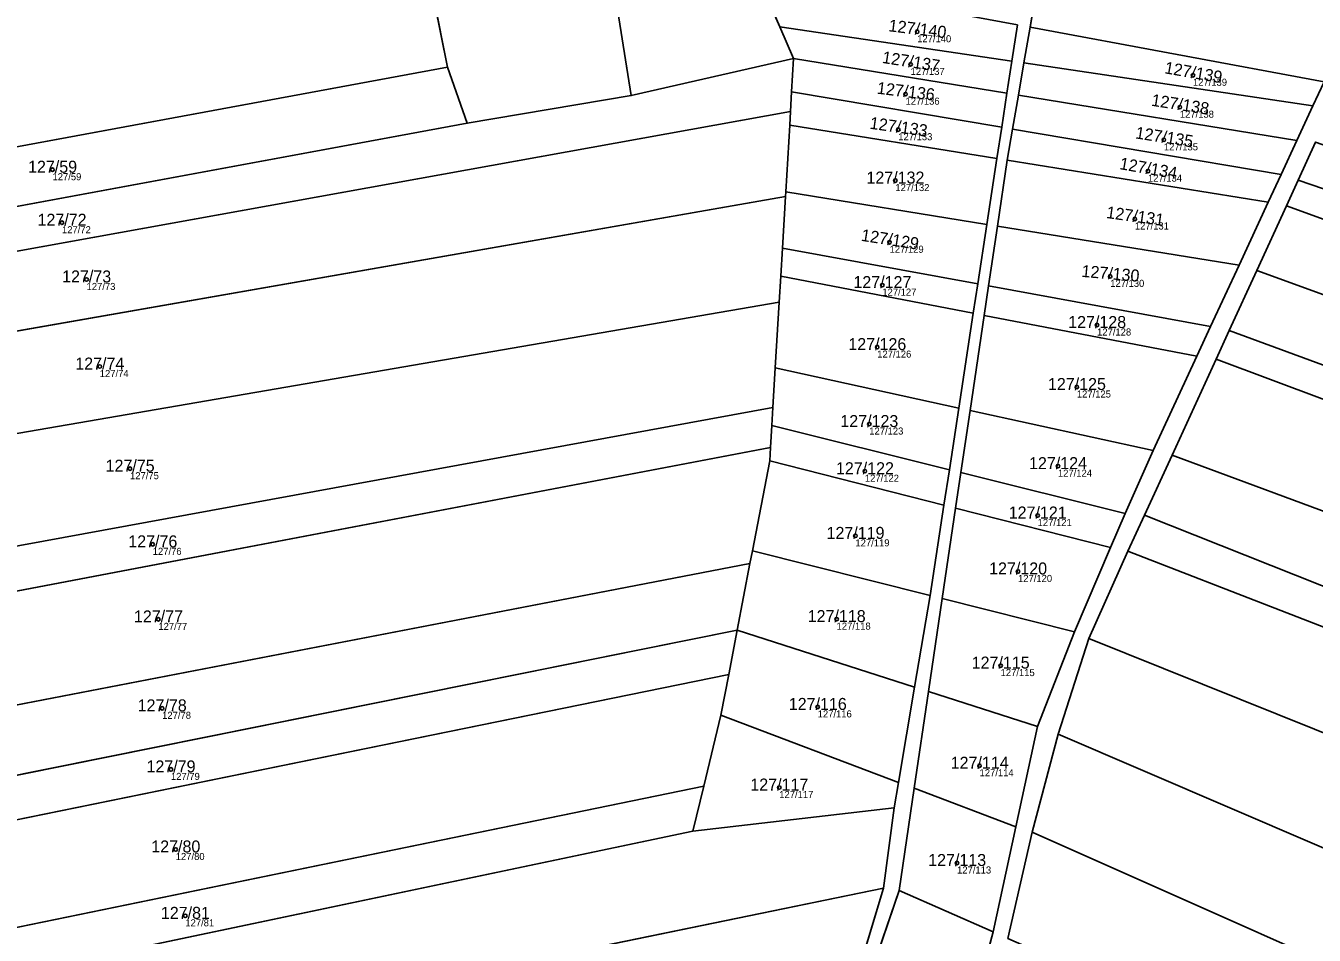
# Model space of a CAD drawing. Extents: x -603967 to -594699, y -1179315 to -1165625.
# Drawn here: x -597682 to -597499.3, y -1173222.3 to -1173093.3 of the extents above; entities that cross this region are included whole.
import ezdxf

# ---------------------------------------------------------------- set-up
doc = ezdxf.new("R2010")
doc.units = 0
for name, color, linetype in [('Definiční body', 7, 'Continuous'), ('Hranice parcel', 7, 'Continuous'), ('Parcelní čísla', 7, 'Continuous'), ('Polygon parcely', 7, 'Continuous')]:
    doc.layers.add(name, color=color, linetype=linetype)

msp = doc.modelspace()

# ---------------------------------------------------------------- linework, layer by layer
at = {"layer": 'Definiční body'}
for centre in [(-597555.59, -1173094.17994), (-597556.52, -1173098.80994), (-597516.49, -1173100.34994), (-597557.24, -1173103.02994), (-597518.35, -1173104.87994), (-597558.27, -1173108.06994), (-597520.61, -1173109.50994), (-597678.17, -1173113.73994), (-597522.87, -1173113.93994), (-597558.68, -1173115.27994), (-597676.83, -1173121.25994), (-597524.73, -1173120.72994), (-597559.5, -1173124.02994), (-597528.22, -1173128.85994), (-597673.34, -1173129.29994), (-597560.53, -1173130.09994), (-597530.08, -1173135.75994), (-597561.25, -1173138.88994), (-597671.47, -1173141.64994), (-597532.95, -1173144.54994), (-597562.38, -1173149.79994), (-597667.18, -1173156.12994), (-597535.63, -1173155.76994), (-597563, -1173156.48994), (-597538.51, -1173162.76994), (-597663.96, -1173166.85994), (-597564.34, -1173165.65994), (-597541.29, -1173170.69994), (-597663.16, -1173177.49994), (-597567.01, -1173177.45994), (-597543.76, -1173184.04994), (-597662.63, -1173190.10994), (-597569.69, -1173189.90994), (-597546.74, -1173198.24994), (-597661.38, -1173198.76994), (-597575.14, -1173201.33994), (-597660.7, -1173210.11994), (-597549.93, -1173212.03994), (-597659.34, -1173219.52994)]:
    msp.add_circle(centre, 0.25, dxfattribs=at)
at = {"layer": 'Hranice parcel'}
for p, q in [((-597596.13, -1173103.22), (-597600.77, -1173074)), ((-597622.15, -1173099.18), (-597626.8, -1173076.25)), ((-597537.26, -1173079.97), (-597539.59, -1173093.53)), ((-597575.07, -1173093.46), (-597577.07, -1173088.83)), ((-597542.16, -1173098.34), (-597575.07, -1173093.46)), ((-597573.1, -1173097.99), (-597575.07, -1173093.46)), ((-597542.16, -1173098.34), (-597541.37, -1173093.2)), ((-597539.59, -1173093.53), (-597540.46, -1173098.59)), ((-597497.91, -1173101.27), (-597539.59, -1173093.53)), ((-597763.28, -1173125.31), (-597622.15, -1173099.18)), ((-597619.36, -1173107.15), (-597622.15, -1173099.18)), ((-597596.13, -1173103.22), (-597573.1, -1173097.99)), ((-597573.38, -1173102.7), (-597573.1, -1173097.99)), ((-597542.86, -1173102.9), (-597573.1, -1173097.99)), ((-597542.86, -1173102.9), (-597542.16, -1173098.34)), ((-597540.46, -1173098.59), (-597541.24, -1173103.16)), ((-597499.48, -1173104.67), (-597540.46, -1173098.59)), ((-597499.48, -1173104.67), (-597497.91, -1173101.27)), ((-597573.54, -1173105.47), (-597573.38, -1173102.7)), ((-597543.6, -1173107.73), (-597573.38, -1173102.7)), ((-597543.6, -1173107.73), (-597542.86, -1173102.9)), ((-597619.36, -1173107.15), (-597596.13, -1173103.22)), ((-597541.24, -1173103.16), (-597542.07, -1173107.99)), ((-597501.75, -1173109.58), (-597541.24, -1173103.16)), ((-597501.75, -1173109.58), (-597499.48, -1173104.67)), ((-597764.61, -1173139.97), (-597573.54, -1173105.47)), ((-597573.66, -1173107.41), (-597573.54, -1173105.47)), ((-597764.06, -1173133.88), (-597619.36, -1173107.15)), ((-597574.22, -1173116.88), (-597573.66, -1173107.41)), ((-597544.28, -1173112.15), (-597573.66, -1173107.41)), ((-597544.28, -1173112.15), (-597543.6, -1173107.73)), ((-597542.07, -1173107.99), (-597542.82, -1173112.39)), ((-597503.99, -1173114.42), (-597542.07, -1173107.99)), ((-597503.99, -1173114.42), (-597501.75, -1173109.58)), ((-597499.11, -1173109.82), (-597501.58, -1173115.24)), ((-597545.71, -1173121.49), (-597544.28, -1173112.15)), ((-597542.82, -1173112.39), (-597544.21, -1173121.73)), ((-597505.82, -1173118.36), (-597542.82, -1173112.39)), ((-597505.82, -1173118.36), (-597503.99, -1173114.42)), ((-597501.58, -1173115.24), (-597503.24, -1173118.85)), ((-597765.61, -1173151.05), (-597574.26, -1173117.53)), ((-597574.69, -1173124.84), (-597574.26, -1173117.53)), ((-597574.26, -1173117.53), (-597574.22, -1173116.88)), ((-597545.71, -1173121.49), (-597574.22, -1173116.88)), ((-597509.95, -1173127.26), (-597505.82, -1173118.36)), ((-597503.24, -1173118.85), (-597507.45, -1173128.03)), ((-597547, -1173129.92), (-597545.71, -1173121.49)), ((-597544.21, -1173121.73), (-597545.46, -1173130.2)), ((-597509.95, -1173127.26), (-597544.21, -1173121.73)), ((-597574.93, -1173128.85), (-597574.69, -1173124.84)), ((-597547, -1173129.92), (-597574.69, -1173124.84)), ((-597513.99, -1173135.97), (-597509.95, -1173127.26)), ((-597507.45, -1173128.03), (-597511.35, -1173136.53)), ((-597575.15, -1173132.5), (-597574.93, -1173128.85)), ((-597547.64, -1173134.09), (-597574.93, -1173128.85)), ((-597547.64, -1173134.09), (-597547, -1173129.92)), ((-597545.46, -1173130.2), (-597546.08, -1173134.39)), ((-597513.99, -1173135.97), (-597545.46, -1173130.2)), ((-597575.7, -1173141.84), (-597575.15, -1173132.5)), ((-597549.69, -1173147.54), (-597547.64, -1173134.09)), ((-597546.08, -1173134.39), (-597548.08, -1173147.89)), ((-597515.94, -1173140.18), (-597546.08, -1173134.39)), ((-597515.94, -1173140.18), (-597513.99, -1173135.97)), ((-597511.35, -1173136.53), (-597513.22, -1173140.6)), ((-597522.14, -1173153.57), (-597515.94, -1173140.18)), ((-597513.22, -1173140.6), (-597519.45, -1173154.19)), ((-597576.04, -1173147.45), (-597575.7, -1173141.84)), ((-597549.69, -1173147.54), (-597575.7, -1173141.84)), ((-597576.19, -1173150.01), (-597576.04, -1173147.45)), ((-597551.02, -1173156.28), (-597549.69, -1173147.54)), ((-597548.08, -1173147.89), (-597549.38, -1173156.69)), ((-597522.14, -1173153.57), (-597548.08, -1173147.89)), ((-597576.38, -1173153.11), (-597576.19, -1173150.01)), ((-597551.02, -1173156.28), (-597576.19, -1173150.01)), ((-597769.12, -1173189.83), (-597576.38, -1173153.11)), ((-597576.49, -1173155.03), (-597576.38, -1173153.11)), ((-597526.08, -1173162.49), (-597522.14, -1173153.57)), ((-597519.45, -1173154.19), (-597523.36, -1173162.71)), ((-597578.94, -1173167.78), (-597576.49, -1173155.03)), ((-597551.79, -1173161.31), (-597576.49, -1173155.03)), ((-597551.79, -1173161.31), (-597551.02, -1173156.28)), ((-597549.38, -1173156.69), (-597550.13, -1173161.73)), ((-597526.08, -1173162.49), (-597549.38, -1173156.69)), ((-597553.75, -1173174.1), (-597551.79, -1173161.31)), ((-597550.13, -1173161.73), (-597552.03, -1173174.53)), ((-597528.2, -1173167.3), (-597550.13, -1173161.73)), ((-597528.2, -1173167.3), (-597526.08, -1173162.49)), ((-597523.36, -1173162.71), (-597525.71, -1173167.84)), ((-597579.29, -1173169.58), (-597578.94, -1173167.78)), ((-597553.75, -1173174.1), (-597578.94, -1173167.78)), ((-597533.26, -1173179.25), (-597528.2, -1173167.3)), ((-597525.71, -1173167.84), (-597531.27, -1173180.19)), ((-597770.63, -1173206.5), (-597579.29, -1173169.58)), ((-597581.1, -1173179.02), (-597579.29, -1173169.58)), ((-597555.95, -1173187.09), (-597553.75, -1173174.1)), ((-597552.03, -1173174.53), (-597553.98, -1173187.72)), ((-597533.26, -1173179.25), (-597552.03, -1173174.53)), ((-597771.62, -1173217.4), (-597581.1, -1173179.02)), ((-597582.31, -1173185.32), (-597581.1, -1173179.02)), ((-597555.95, -1173187.09), (-597581.1, -1173179.02)), ((-597538.55, -1173192.67), (-597533.26, -1173179.25)), ((-597531.27, -1173180.19), (-597535.59, -1173193.78)), ((-597772.22, -1173224.08), (-597582.31, -1173185.32)), ((-597583.42, -1173191.09), (-597582.31, -1173185.32)), ((-597558.24, -1173200.61), (-597555.95, -1173187.09)), ((-597553.98, -1173187.72), (-597556.01, -1173201.45)), ((-597538.55, -1173192.67), (-597553.98, -1173187.72)), ((-597585.85, -1173201.13), (-597583.42, -1173191.09)), ((-597583.42, -1173191.09), (-597558.24, -1173200.61)), ((-597541.61, -1173206.89), (-597538.55, -1173192.67)), ((-597535.59, -1173193.78), (-597539.27, -1173207.67)), ((-597773.64, -1173239.78), (-597585.85, -1173201.13)), ((-597587.4, -1173207.52), (-597585.85, -1173201.13)), ((-597558.84, -1173204.24), (-597558.24, -1173200.61)), ((-597556.01, -1173201.45), (-597558.16, -1173215.95)), ((-597541.61, -1173206.89), (-597556.01, -1173201.45)), ((-597558.84, -1173204.24), (-597587.4, -1173207.52)), ((-597560.35, -1173215.6), (-597558.84, -1173204.24)), ((-597544.83, -1173221.82), (-597541.61, -1173206.89)), ((-597774.27, -1173246.79), (-597587.4, -1173207.52)), ((-597539.27, -1173207.67), (-597542.73, -1173222.74)), ((-597775.45, -1173259.82), (-597560.35, -1173215.6)), ((-597564.2, -1173228.37), (-597560.35, -1173215.6)), ((-597558.16, -1173215.95), (-597562.03, -1173227.35)), ((-597544.83, -1173221.82), (-597558.16, -1173215.95)), ((-597547.95, -1173233.43), (-597544.83, -1173221.82))]:
    msp.add_line(p, q, dxfattribs=at)
for points in [[(-597501.58, -1173115.24), (-597411.51, -1173146.02), (-597392.58, -1173150.97)], [(-597503.24, -1173118.85), (-597413.15, -1173151.58), (-597393.21, -1173156.65)], [(-597507.45, -1173128.03), (-597413.15, -1173162.29), (-597393.22, -1173166.52)], [(-597767.08, -1173167.25), (-597709.6, -1173155.67), (-597575.15, -1173132.5)], [(-597511.35, -1173136.53), (-597413.98, -1173172.37), (-597394.05, -1173178.28)], [(-597513.22, -1173140.6), (-597414.59, -1173177.52), (-597394.47, -1173184.52)], [(-597768.63, -1173184.38), (-597738.82, -1173177.3), (-597576.04, -1173147.45)], [(-597519.45, -1173154.19), (-597436.78, -1173184.85), (-597395, -1173200.4)], [(-597523.36, -1173162.71), (-597469.7, -1173184.02), (-597395.32, -1173209.93)], [(-597525.71, -1173167.84), (-597460.65, -1173193.08), (-597397.53, -1173216.17)], [(-597531.27, -1173180.19), (-597472.58, -1173203.79), (-597402.11, -1173229.07)], [(-597535.59, -1173193.78), (-597474.9, -1173219.8), (-597408.96, -1173247.24)], [(-597539.27, -1173207.67), (-597474.86, -1173236.29), (-597414.15, -1173260.99)]]:
    msp.add_lwpolyline(points, dxfattribs=at)
at = {"layer": 'Polygon parcely'}
for points in [[(-597562.03, -1173227.35), (-597558.16, -1173215.95), (-597556.01, -1173201.45), (-597553.98, -1173187.72), (-597552.03, -1173174.53), (-597550.13, -1173161.73), (-597549.38, -1173156.69), (-597548.08, -1173147.89), (-597546.08, -1173134.39), (-597545.46, -1173130.2), (-597544.21, -1173121.73), (-597542.82, -1173112.39), (-597542.07, -1173107.99), (-597541.24, -1173103.16), (-597540.46, -1173098.59), (-597539.59, -1173093.53), (-597537.26, -1173079.97), (-597535.02, -1173066.92), (-597532.9, -1173054.55)], [(-597541.37, -1173093.2), (-597542.16, -1173098.34), (-597542.86, -1173102.9), (-597543.6, -1173107.73), (-597544.28, -1173112.15), (-597545.71, -1173121.49), (-597547, -1173129.92), (-597547.64, -1173134.09), (-597549.69, -1173147.54), (-597551.02, -1173156.28), (-597551.79, -1173161.31), (-597553.75, -1173174.1), (-597555.95, -1173187.09), (-597558.24, -1173200.61), (-597558.84, -1173204.24), (-597560.35, -1173215.6), (-597564.2, -1173228.37)], [(-597497.91, -1173101.27), (-597499.48, -1173104.67), (-597501.75, -1173109.58), (-597503.99, -1173114.42), (-597505.82, -1173118.36), (-597509.95, -1173127.26), (-597513.99, -1173135.97), (-597515.94, -1173140.18), (-597522.14, -1173153.57), (-597526.08, -1173162.49), (-597528.2, -1173167.3), (-597533.26, -1173179.25), (-597538.55, -1173192.67), (-597541.61, -1173206.89), (-597544.83, -1173221.82), (-597547.95, -1173233.43)], [(-597542.73, -1173222.74), (-597539.27, -1173207.67), (-597535.59, -1173193.78), (-597531.27, -1173180.19), (-597525.71, -1173167.84), (-597523.36, -1173162.71), (-597519.45, -1173154.19), (-597513.22, -1173140.6), (-597511.35, -1173136.53), (-597507.45, -1173128.03), (-597503.24, -1173118.85), (-597501.58, -1173115.24), (-597499.11, -1173109.82)]]:
    msp.add_lwpolyline(points, dxfattribs=at)
for points in [[(-597575.07, -1173093.46), (-597577.07, -1173088.83), (-597581.97, -1173072.38), (-597600.77, -1173074), (-597596.13, -1173103.22), (-597573.1, -1173097.99)], [(-597596.13, -1173103.22), (-597600.77, -1173074), (-597626.8, -1173076.25), (-597622.15, -1173099.18), (-597619.36, -1173107.15)], [(-597763.28, -1173125.31), (-597622.15, -1173099.18), (-597626.8, -1173076.25), (-597761.18, -1173102.14)], [(-597497.91, -1173101.27), (-597490.13, -1173088.07), (-597537.26, -1173079.97), (-597539.59, -1173093.53)], [(-597541.37, -1173093.2), (-597556.53, -1173090.39), (-597577.07, -1173088.83), (-597575.07, -1173093.46), (-597542.16, -1173098.34)], [(-597542.16, -1173098.34), (-597575.07, -1173093.46), (-597573.1, -1173097.99), (-597542.86, -1173102.9)], [(-597499.48, -1173104.67), (-597497.91, -1173101.27), (-597539.59, -1173093.53), (-597540.46, -1173098.59)], [(-597573.38, -1173102.7), (-597573.1, -1173097.99), (-597596.13, -1173103.22), (-597619.36, -1173107.15), (-597764.06, -1173133.88), (-597764.61, -1173139.97), (-597573.54, -1173105.47)], [(-597763.28, -1173125.31), (-597764.06, -1173133.88), (-597619.36, -1173107.15), (-597622.15, -1173099.18)], [(-597542.86, -1173102.9), (-597573.1, -1173097.99), (-597573.38, -1173102.7), (-597543.6, -1173107.73)], [(-597501.75, -1173109.58), (-597499.48, -1173104.67), (-597540.46, -1173098.59), (-597541.24, -1173103.16)], [(-597544.28, -1173112.15), (-597543.6, -1173107.73), (-597573.38, -1173102.7), (-597573.54, -1173105.47), (-597573.66, -1173107.41)], [(-597501.75, -1173109.58), (-597541.24, -1173103.16), (-597542.07, -1173107.99), (-597503.99, -1173114.42)], [(-597764.61, -1173139.97), (-597765.61, -1173151.05), (-597574.26, -1173117.53), (-597574.22, -1173116.88), (-597573.66, -1173107.41), (-597573.54, -1173105.47)], [(-597545.71, -1173121.49), (-597544.28, -1173112.15), (-597573.66, -1173107.41), (-597574.22, -1173116.88)], [(-597505.82, -1173118.36), (-597503.99, -1173114.42), (-597542.07, -1173107.99), (-597542.82, -1173112.39)], [(-597392.58, -1173150.97), (-597392, -1173145.76), (-597412.33, -1173140.05), (-597499.11, -1173109.82), (-597501.58, -1173115.24), (-597411.51, -1173146.02)], [(-597544.21, -1173121.73), (-597509.95, -1173127.26), (-597505.82, -1173118.36), (-597542.82, -1173112.39)], [(-597393.21, -1173156.65), (-597392.58, -1173150.97), (-597411.51, -1173146.02), (-597501.58, -1173115.24), (-597503.24, -1173118.85), (-597413.15, -1173151.58)], [(-597575.15, -1173132.5), (-597574.93, -1173128.85), (-597574.69, -1173124.84), (-597574.26, -1173117.53), (-597765.61, -1173151.05), (-597767.08, -1173167.25), (-597709.6, -1173155.67)], [(-597547, -1173129.92), (-597545.71, -1173121.49), (-597574.22, -1173116.88), (-597574.26, -1173117.53), (-597574.69, -1173124.84)], [(-597393.22, -1173166.52), (-597393.21, -1173156.65), (-597413.15, -1173151.58), (-597503.24, -1173118.85), (-597507.45, -1173128.03), (-597413.15, -1173162.29)], [(-597509.95, -1173127.26), (-597544.21, -1173121.73), (-597545.46, -1173130.2), (-597513.99, -1173135.97)], [(-597547, -1173129.92), (-597574.69, -1173124.84), (-597574.93, -1173128.85), (-597547.64, -1173134.09)], [(-597413.98, -1173172.37), (-597394.05, -1173178.28), (-597393.22, -1173166.52), (-597413.15, -1173162.29), (-597507.45, -1173128.03), (-597511.35, -1173136.53)], [(-597547.64, -1173134.09), (-597574.93, -1173128.85), (-597575.15, -1173132.5), (-597575.7, -1173141.84), (-597549.69, -1173147.54)], [(-597546.08, -1173134.39), (-597515.94, -1173140.18), (-597513.99, -1173135.97), (-597545.46, -1173130.2)], [(-597767.08, -1173167.25), (-597768.63, -1173184.38), (-597738.82, -1173177.3), (-597576.04, -1173147.45), (-597575.7, -1173141.84), (-597575.15, -1173132.5), (-597709.6, -1173155.67)], [(-597515.94, -1173140.18), (-597546.08, -1173134.39), (-597548.08, -1173147.89), (-597522.14, -1173153.57)], [(-597414.59, -1173177.52), (-597394.47, -1173184.52), (-597394.05, -1173178.28), (-597413.98, -1173172.37), (-597511.35, -1173136.53), (-597513.22, -1173140.6)], [(-597436.78, -1173184.85), (-597395, -1173200.4), (-597394.47, -1173184.52), (-597414.59, -1173177.52), (-597513.22, -1173140.6), (-597519.45, -1173154.19)], [(-597551.02, -1173156.28), (-597549.69, -1173147.54), (-597575.7, -1173141.84), (-597576.04, -1173147.45), (-597576.19, -1173150.01)], [(-597576.19, -1173150.01), (-597576.04, -1173147.45), (-597738.82, -1173177.3), (-597768.63, -1173184.38), (-597769.12, -1173189.83), (-597576.38, -1173153.11)], [(-597522.14, -1173153.57), (-597548.08, -1173147.89), (-597549.38, -1173156.69), (-597526.08, -1173162.49)], [(-597551.79, -1173161.31), (-597551.02, -1173156.28), (-597576.19, -1173150.01), (-597576.38, -1173153.11), (-597576.49, -1173155.03)], [(-597578.94, -1173167.78), (-597576.49, -1173155.03), (-597576.38, -1173153.11), (-597769.12, -1173189.83), (-597770.63, -1173206.5), (-597579.29, -1173169.58)], [(-597395.32, -1173209.93), (-597395, -1173200.4), (-597436.78, -1173184.85), (-597519.45, -1173154.19), (-597523.36, -1173162.71), (-597469.7, -1173184.02)], [(-597551.79, -1173161.31), (-597576.49, -1173155.03), (-597578.94, -1173167.78), (-597553.75, -1173174.1)], [(-597526.08, -1173162.49), (-597549.38, -1173156.69), (-597550.13, -1173161.73), (-597528.2, -1173167.3)], [(-597552.03, -1173174.53), (-597533.26, -1173179.25), (-597528.2, -1173167.3), (-597550.13, -1173161.73)], [(-597397.53, -1173216.17), (-597395.32, -1173209.93), (-597469.7, -1173184.02), (-597523.36, -1173162.71), (-597525.71, -1173167.84), (-597460.65, -1173193.08)], [(-597553.75, -1173174.1), (-597578.94, -1173167.78), (-597579.29, -1173169.58), (-597581.1, -1173179.02), (-597555.95, -1173187.09)], [(-597402.11, -1173229.07), (-597397.53, -1173216.17), (-597460.65, -1173193.08), (-597525.71, -1173167.84), (-597531.27, -1173180.19), (-597472.58, -1173203.79)], [(-597581.1, -1173179.02), (-597579.29, -1173169.58), (-597770.63, -1173206.5), (-597771.62, -1173217.4)], [(-597553.98, -1173187.72), (-597538.55, -1173192.67), (-597533.26, -1173179.25), (-597552.03, -1173174.53)], [(-597582.31, -1173185.32), (-597581.1, -1173179.02), (-597771.62, -1173217.4), (-597772.22, -1173224.08)], [(-597555.95, -1173187.09), (-597581.1, -1173179.02), (-597582.31, -1173185.32), (-597583.42, -1173191.09), (-597558.24, -1173200.61)], [(-597408.96, -1173247.24), (-597402.11, -1173229.07), (-597472.58, -1173203.79), (-597531.27, -1173180.19), (-597535.59, -1173193.78), (-597474.9, -1173219.8)], [(-597772.22, -1173224.08), (-597773.64, -1173239.78), (-597585.85, -1173201.13), (-597583.42, -1173191.09), (-597582.31, -1173185.32)], [(-597538.55, -1173192.67), (-597553.98, -1173187.72), (-597556.01, -1173201.45), (-597541.61, -1173206.89)], [(-597558.24, -1173200.61), (-597583.42, -1173191.09), (-597585.85, -1173201.13), (-597587.4, -1173207.52), (-597558.84, -1173204.24)], [(-597539.27, -1173207.67), (-597474.86, -1173236.29), (-597414.15, -1173260.99), (-597408.96, -1173247.24), (-597474.9, -1173219.8), (-597535.59, -1173193.78)], [(-597773.64, -1173239.78), (-597774.27, -1173246.79), (-597587.4, -1173207.52), (-597585.85, -1173201.13)], [(-597541.61, -1173206.89), (-597556.01, -1173201.45), (-597558.16, -1173215.95), (-597544.83, -1173221.82)], [(-597558.84, -1173204.24), (-597587.4, -1173207.52), (-597774.27, -1173246.79), (-597775.45, -1173259.82), (-597560.35, -1173215.6)], [(-597542.73, -1173222.74), (-597413.7, -1173279.52), (-597414.15, -1173260.99), (-597474.86, -1173236.29), (-597539.27, -1173207.67)], [(-597564.2, -1173228.37), (-597560.35, -1173215.6), (-597775.45, -1173259.82), (-597776.59, -1173272.46)], [(-597547.95, -1173233.43), (-597544.83, -1173221.82), (-597558.16, -1173215.95), (-597562.03, -1173227.35)]]:
    msp.add_lwpolyline(points, close=True, dxfattribs=at)

# ---------------------------------------------------------------- texts
at = {"layer": 'Definiční body'}
for s, p in [('127/140', (-597555.59, -1173095.669)), ('127/137', (-597556.52, -1173100.299)), ('127/139', (-597516.49, -1173101.839)), ('127/136', (-597557.24, -1173104.519)), ('127/138', (-597518.35, -1173106.369)), ('127/133', (-597558.27, -1173109.559)), ('127/135', (-597520.61, -1173110.999)), ('127/59', (-597678.17, -1173115.229)), ('127/132', (-597558.68, -1173116.769)), ('127/134', (-597522.87, -1173115.429)), ('127/131', (-597524.73, -1173122.219)), ('127/72', (-597676.83, -1173122.749)), ('127/129', (-597559.5, -1173125.519)), ('127/73', (-597673.34, -1173130.789)), ('127/127', (-597560.53, -1173131.589)), ('127/130', (-597528.22, -1173130.349)), ('127/128', (-597530.08, -1173137.249)), ('127/126', (-597561.25, -1173140.379)), ('127/74', (-597671.47, -1173143.139)), ('127/125', (-597532.95, -1173146.039)), ('127/123', (-597562.38, -1173151.289)), ('127/75', (-597667.18, -1173157.619)), ('127/122', (-597563, -1173157.979)), ('127/124', (-597535.63, -1173157.259)), ('127/121', (-597538.51, -1173164.259)), ('127/119', (-597564.34, -1173167.149)), ('127/76', (-597663.96, -1173168.349)), ('127/120', (-597541.29, -1173172.189)), ('127/77', (-597663.16, -1173178.989)), ('127/118', (-597567.01, -1173178.949)), ('127/115', (-597543.76, -1173185.539)), ('127/78', (-597662.63, -1173191.599)), ('127/116', (-597569.69, -1173191.399)), ('127/79', (-597661.38, -1173200.259)), ('127/114', (-597546.74, -1173199.739)), ('127/117', (-597575.14, -1173202.829)), ('127/80', (-597660.7, -1173211.609)), ('127/113', (-597549.93, -1173213.529)), ('127/81', (-597659.34, -1173221.019))]:
    msp.add_text(s, height=0.999996, dxfattribs=at).set_placement(p)
at = {"layer": 'Parcelní čísla'}
for s, rotation, p in [('127/140', 353, (-597559.707, -1173094.102)), ('127/137', 351, (-597560.632, -1173098.588)), ('127/139', 349.9999972, (-597520.598, -1173100.057)), ('127/136', 353, (-597561.357, -1173102.952)), ('127/138', 351, (-597522.462, -1173104.658)), ('127/133', 351.9999972, (-597562.385, -1173107.92)), ('127/135', 351, (-597524.722, -1173109.288)), ('127/134', 349.9999972, (-597526.978, -1173113.647)), ('127/131', 351.9999972, (-597528.845, -1173120.58)), ('127/129', 351, (-597563.612, -1173123.808)), ('127/130', 355, (-597532.338, -1173128.926))]:
    msp.add_text(s, height=1.699998, rotation=rotation, dxfattribs=at).set_placement(p)
for s, p in [('127/59', (-597681.636, -1173114.165)), ('127/132', (-597562.776, -1173115.705)), ('127/72', (-597680.296, -1173121.685)), ('127/73', (-597676.806, -1173129.725)), ('127/127', (-597564.626, -1173130.525)), ('127/128', (-597534.176, -1173136.185)), ('127/126', (-597565.346, -1173139.315)), ('127/74', (-597674.936, -1173142.075)), ('127/125', (-597537.046, -1173144.975)), ('127/123', (-597566.476, -1173150.225)), ('127/75', (-597670.646, -1173156.555)), ('127/122', (-597567.096, -1173156.915)), ('127/124', (-597539.726, -1173156.195)), ('127/121', (-597542.606, -1173163.195)), ('127/119', (-597568.436, -1173166.085)), ('127/76', (-597667.426, -1173167.285)), ('127/120', (-597545.386, -1173171.125)), ('127/77', (-597666.626, -1173177.925)), ('127/118', (-597571.106, -1173177.885)), ('127/115', (-597547.856, -1173184.475)), ('127/78', (-597666.096, -1173190.535)), ('127/116', (-597573.786, -1173190.335)), ('127/79', (-597664.846, -1173199.195)), ('127/114', (-597550.836, -1173198.675)), ('127/117', (-597579.236, -1173201.765)), ('127/80', (-597664.166, -1173210.545)), ('127/113', (-597554.026, -1173212.465)), ('127/81', (-597662.806, -1173219.955))]:
    msp.add_text(s, height=1.699998, dxfattribs=at).set_placement(p)

doc.saveas('drawing.dxf')
